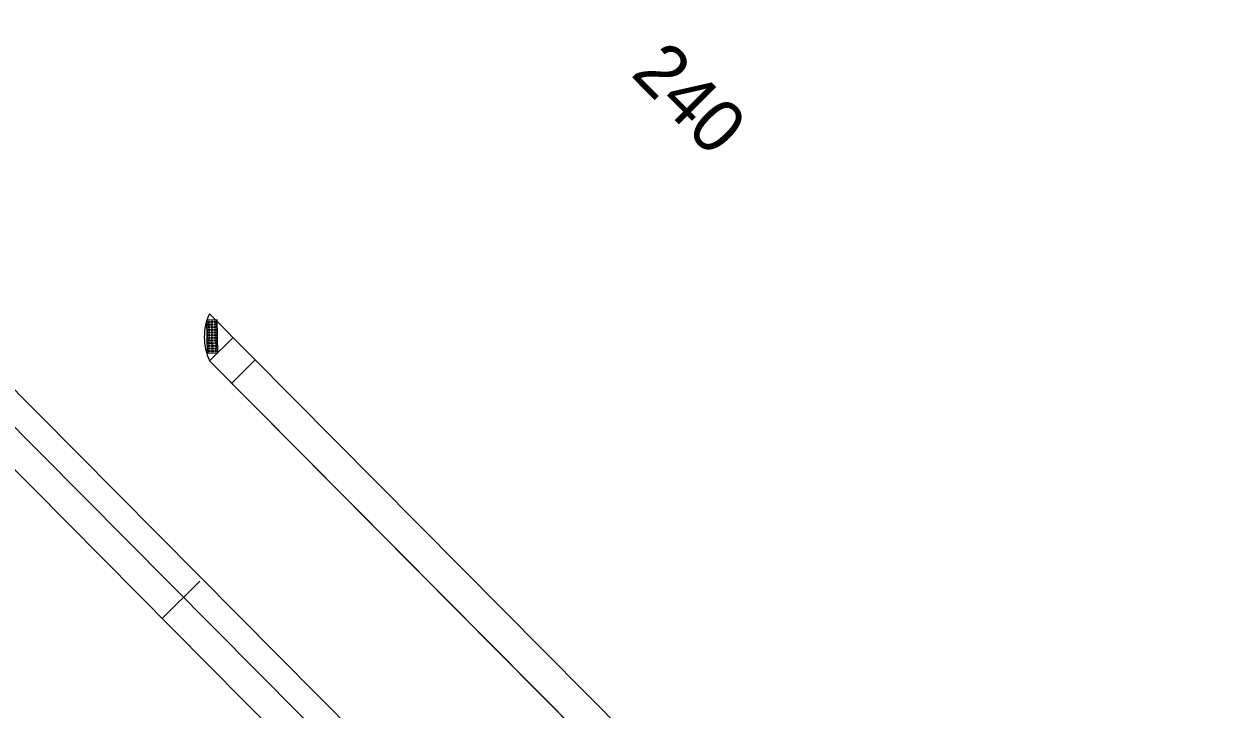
# Model space of a CAD drawing. Extents: x -5665 to 1997148, y 4 to 827579.
# Drawn here: x 1972306.3 to 1972485.9, y 801965 to 802068.6 of the extents above; entities that cross this region are included whole.
import ezdxf

# ---------------------------------------------------------------- set-up
doc = ezdxf.new("R2010")
doc.units = 0
for name, color, linetype in [('RD_HC_CL_Rel', 7, 'Continuous'), ('RD_HC_Data_Tic_Rel', 7, 'Continuous'), ('RD_HC_TX_Rel_Sta50', 7, 'Continuous'), ('RD_PD_SW', 7, 'Continuous')]:
    doc.layers.add(name, color=color, linetype=linetype)

msp = doc.modelspace()

# ---------------------------------------------------------------- linework, layer by layer
at = {"layer": 'RD_HC_CL_Rel'}
msp.add_line((1972119.32, 802188.01), (1972571.34, 801732.96), dxfattribs=at)
at = {"layer": 'RD_HC_Data_Tic_Rel'}
msp.add_line((1972327.22, 801978.71), (1972332.9, 801984.35), dxfattribs=at)
at = {"layer": 'RD_PD_SW'}
for p, q in [((1972334.33, 802024.76), (1972433.73, 801924.7)), ((1972423.87, 801934.63), (1972334.33, 802024.76)), ((1972406, 801911.46), (1972296.09, 802022.11)), ((1972334.37, 802017.64), (1972337.91, 802021.16)), ((1972334.37, 802017.64), (1972430.18, 801921.18)), ((1972334.37, 802017.64), (1972420.33, 801931.1)), ((1972337.71, 802014.27), (1972341.26, 802017.79))]:
    msp.add_line(p, q, dxfattribs=at)
msp.add_lwpolyline([(1972260.13, 802052.64), (1972269.55, 802043.16), (1972400.35, 801911.48), (1972403.17, 801908.64)], dxfattribs=at)
msp.add_lwpolyline([(1972335.62, 802018.85), (1972335.52, 802023.84), (1972333.92, 802023.81), (1972334.02, 802018.82)], close=True, dxfattribs=at)
for centre, radius in [((1972334.22, 802023.51), 0.146), ((1972334.23, 802023.11), 0.146), ((1972334.24, 802022.71), 0.146), ((1972334.22, 802023.51), 0.073), ((1972334.23, 802023.11), 0.073), ((1972334.24, 802022.71), 0.073), ((1972334.72, 802023.52), 0.146), ((1972334.73, 802023.12), 0.146), ((1972334.74, 802022.72), 0.146), ((1972334.72, 802023.52), 0.073), ((1972334.73, 802023.12), 0.073), ((1972334.74, 802022.72), 0.073), ((1972335.23, 802023.53), 0.146), ((1972335.24, 802023.13), 0.146), ((1972335.25, 802022.73), 0.146), ((1972335.23, 802023.53), 0.073), ((1972335.24, 802023.13), 0.073), ((1972335.25, 802022.73), 0.073), ((1972334.25, 802022.31), 0.146), ((1972334.25, 802021.91), 0.146), ((1972334.26, 802021.51), 0.146), ((1972334.27, 802021.11), 0.146), ((1972334.28, 802020.71), 0.146), ((1972334.25, 802022.31), 0.073), ((1972334.25, 802021.91), 0.073), ((1972334.26, 802021.51), 0.073), ((1972334.27, 802021.11), 0.073), ((1972334.28, 802020.71), 0.073), ((1972334.74, 802022.32), 0.146), ((1972334.75, 802021.92), 0.146), ((1972334.76, 802021.52), 0.146), ((1972334.77, 802021.12), 0.146), ((1972334.78, 802020.72), 0.146), ((1972334.74, 802022.32), 0.073), ((1972334.75, 802021.92), 0.073), ((1972334.76, 802021.52), 0.073), ((1972334.77, 802021.12), 0.073), ((1972334.78, 802020.72), 0.073), ((1972335.25, 802022.33), 0.146), ((1972335.26, 802021.93), 0.146), ((1972335.27, 802021.53), 0.146), ((1972335.28, 802021.13), 0.146), ((1972335.28, 802020.73), 0.146), ((1972335.25, 802022.33), 0.073), ((1972335.26, 802021.93), 0.073), ((1972335.27, 802021.53), 0.073), ((1972335.28, 802021.13), 0.073), ((1972335.28, 802020.73), 0.073), ((1972334.28, 802020.31), 0.146), ((1972334.29, 802019.91), 0.146), ((1972334.3, 802019.51), 0.146), ((1972334.31, 802019.11), 0.146), ((1972334.28, 802020.31), 0.073), ((1972334.29, 802019.91), 0.073), ((1972334.3, 802019.51), 0.073), ((1972334.31, 802019.11), 0.073), ((1972334.78, 802020.32), 0.146), ((1972334.79, 802019.92), 0.146), ((1972334.8, 802019.52), 0.146), ((1972334.81, 802019.12), 0.146), ((1972334.78, 802020.32), 0.073), ((1972334.79, 802019.92), 0.073), ((1972334.8, 802019.52), 0.073), ((1972334.81, 802019.12), 0.073), ((1972335.29, 802020.33), 0.146), ((1972335.3, 802019.93), 0.146), ((1972335.31, 802019.53), 0.146), ((1972335.32, 802019.13), 0.146), ((1972335.29, 802020.33), 0.073), ((1972335.3, 802019.93), 0.073), ((1972335.31, 802019.53), 0.073), ((1972335.32, 802019.13), 0.073)]:
    msp.add_circle(centre, radius, dxfattribs=at)
msp.add_arc((1972342.07, 802021.24), 8.5, 155.4764, 205.0592, dxfattribs=at)

# ---------------------------------------------------------------- texts
at = {"layer": 'RD_HC_TX_Rel_Sta50'}
msp.add_text('240', height=8, rotation=314.8091, dxfattribs=at).set_placement((1972397.85, 802060.86))

doc.saveas('drawing.dxf')
